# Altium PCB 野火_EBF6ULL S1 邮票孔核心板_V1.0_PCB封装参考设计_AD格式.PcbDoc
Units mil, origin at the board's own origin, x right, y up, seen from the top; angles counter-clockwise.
Board outline 50000 x 50000 mil, 2 copper layers (Signal, Signal #001), stack 10.4 mil thick; 1 components, 2 nets, 140 pads, 0 vias.
Unrouted connection lines stored in the file: 18.
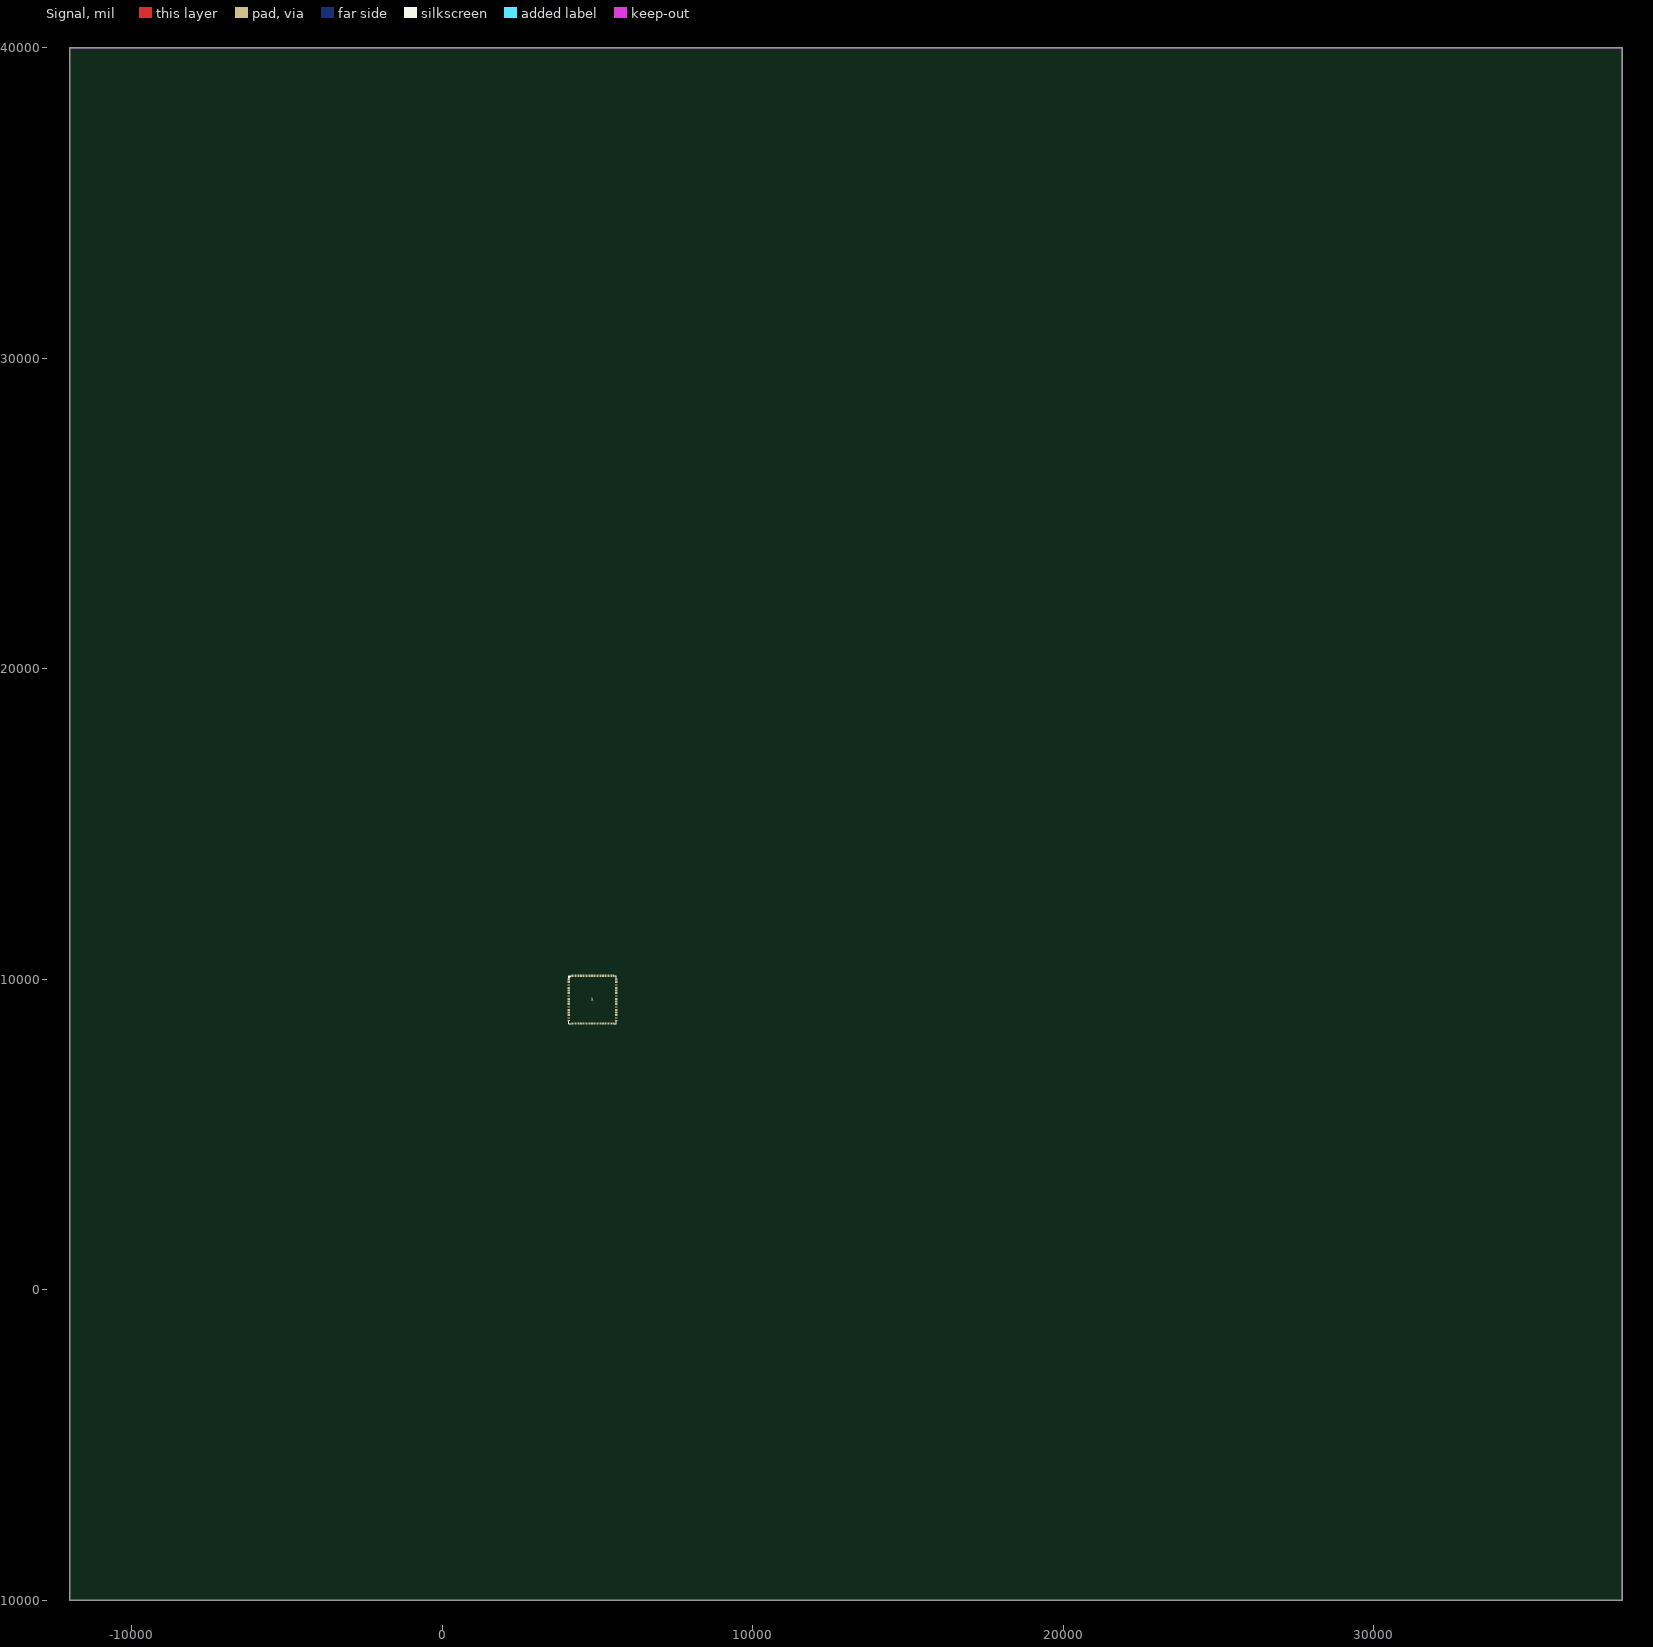
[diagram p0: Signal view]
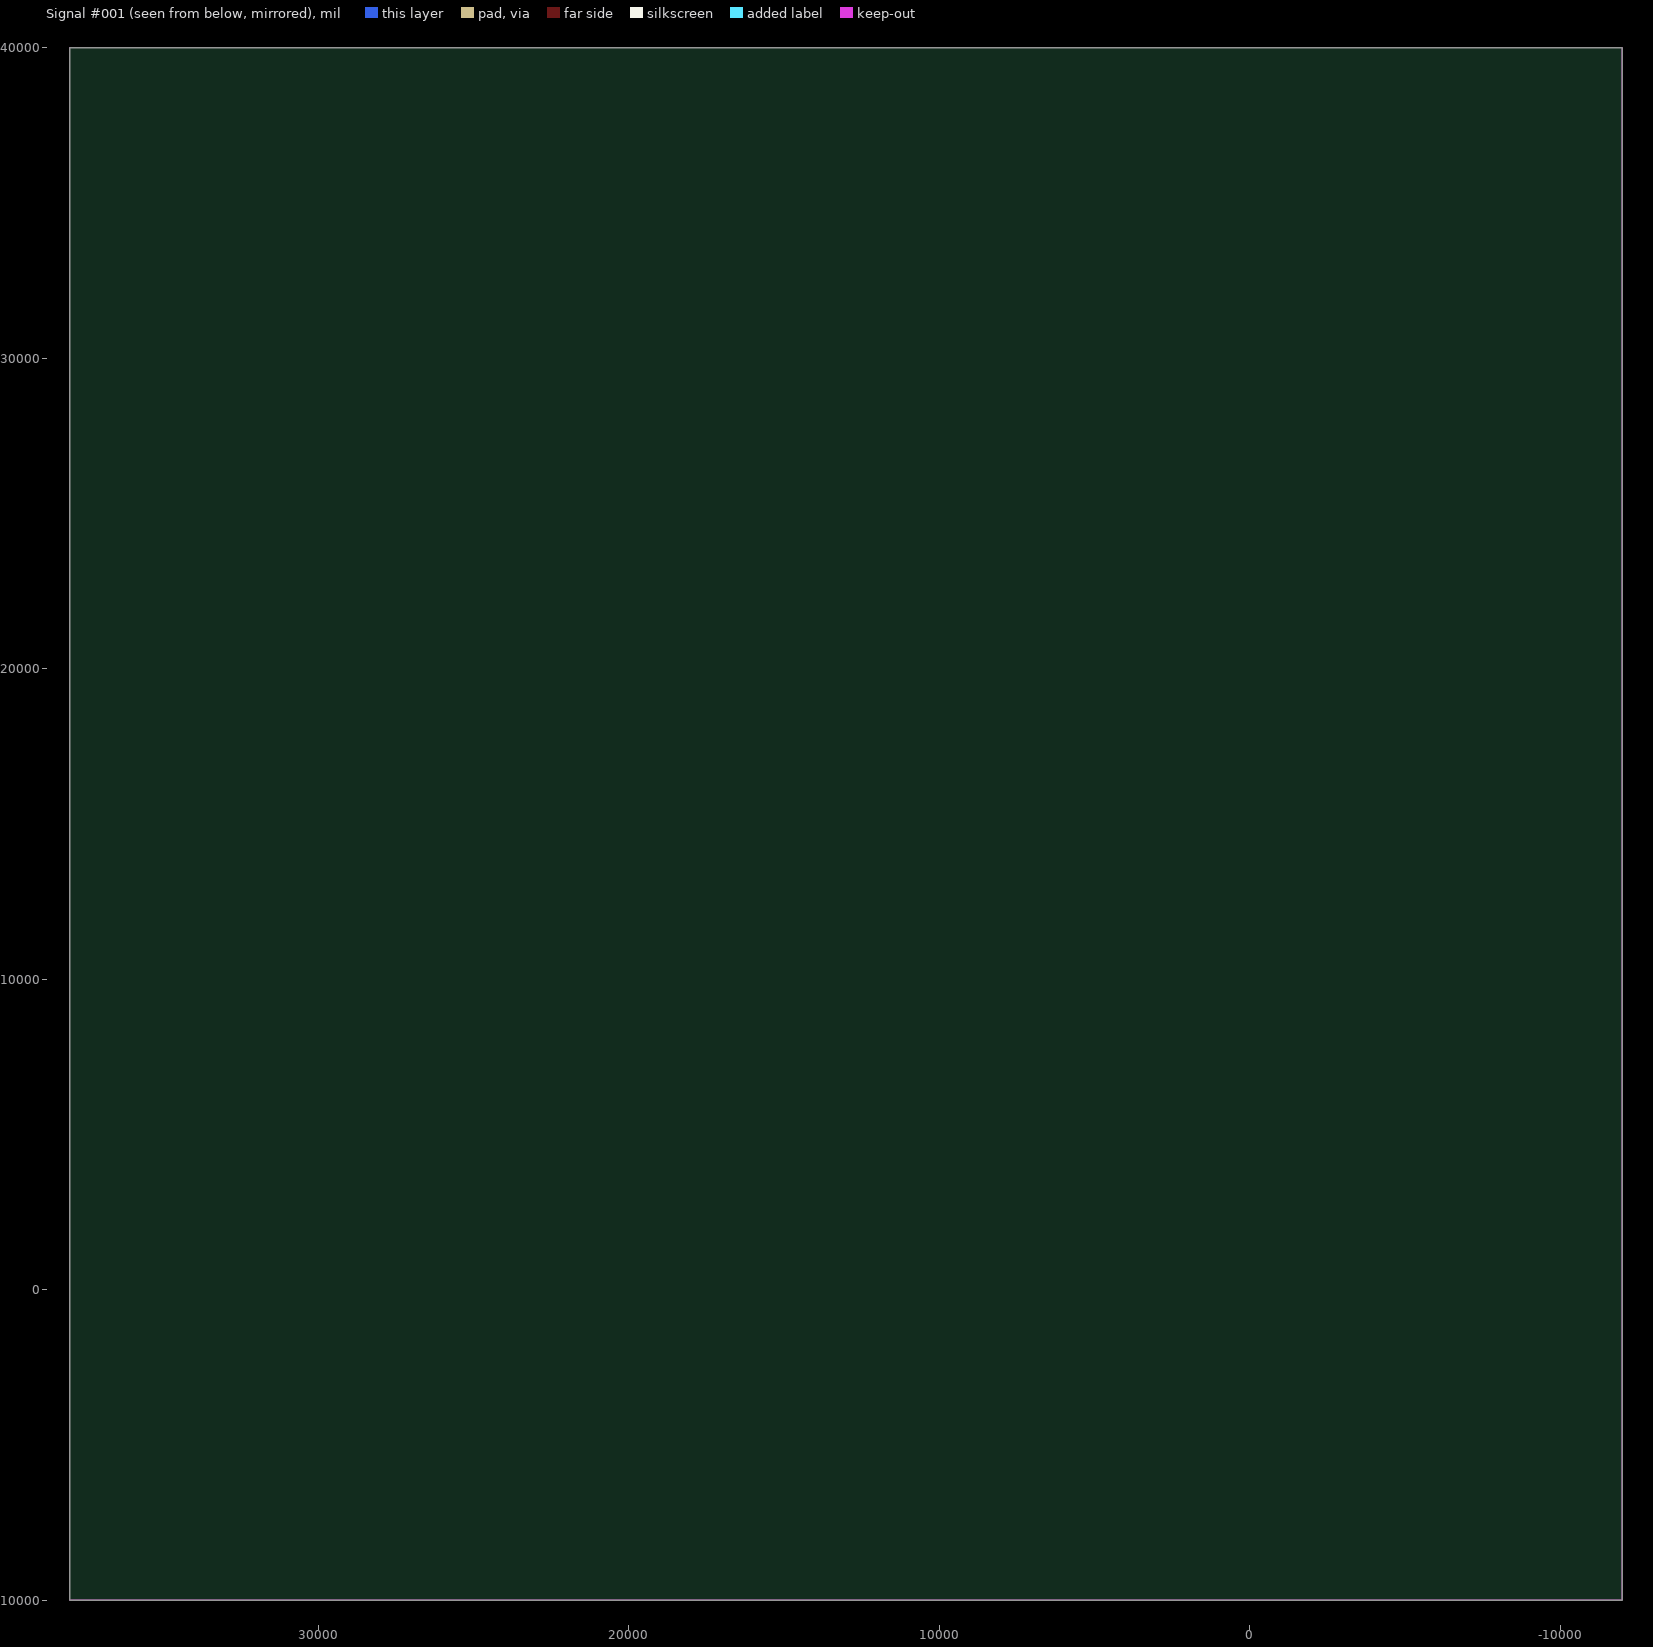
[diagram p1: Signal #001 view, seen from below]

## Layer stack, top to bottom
Solder Mask Top: solder mask 0.4, Solder Resist, Dk 3.5
Signal: signal copper 1.2
Dielectric 1: dielectric 8, FR-4, Dk 4.5
Signal #001: signal copper 1.2
Solder Mask Bottom: solder mask 0.4, Solder Resist, Dk 3.5

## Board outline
-12000,-10000 38000,-10000 38000,40000 -12000,40000

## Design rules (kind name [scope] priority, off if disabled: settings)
Clearance "Clearance - Net - GND- SMD" [InNet('GND') AND IsVia vs IsSMTPin] p1: gap=6 ignorepadtopadclearanceinfootprint=FALSE
Clearance "Clearance - Net - GND - Via" [InNet('GND') And IsVia vs IsVia] p2: gap=6 ignorepadtopadclearanceinfootprint=FALSE
Clearance "Clearance - Net - GND" [InNet('GND')] p3: gap=6 ignorepadtopadclearanceinfootprint=FALSE except(0: Arc-Hole Track-Hole SMDPad-Hole THPad-Hole Via-Hole Fill-Hole Poly-Hole Region-Hole Text-Hole; 8: Via-Fill Via-Poly Via-Region; 10: Fill-Fill Fill-Poly Fill-Region Poly-Poly Poly-Region Region-Region Text-Text; 15: Arc-Fill Arc-Poly Arc-Region Track-Fill Track-Poly Track-Region SMDPad-Fill SMDPad-Poly SMDPad-Region THPad-Fill THPad-Poly THPad-Region)
Clearance "Clearance - Default - DEFAULT- SMD" [IsVia vs IsSMTPin] p4: gap=5 ignorepadtopadclearanceinfootprint=FALSE
Clearance "Clearance - Default - DEFAULT - Via" [IsVia vs IsVia] p5: gap=5 ignorepadtopadclearanceinfootprint=FALSE
Clearance "Clearance - Default - DEFAULT - Net" [All] p6: gap=6 ignorepadtopadclearanceinfootprint=FALSE except(0: Arc-Hole Track-Hole SMDPad-Hole THPad-Hole Via-Hole Fill-Hole Poly-Hole Region-Hole Text-Hole; 5: Via-Via; 8: Via-Fill Via-Poly Via-Region; 10: SMDPad-Fill SMDPad-Poly SMDPad-Region THPad-Fill THPad-Poly THPad-Region Fill-Fill Fill-Poly Fill-Region Poly-Poly Poly-Region Region-Region Text-Text; 15: Arc-Fill Arc-Poly Arc-Region Track-Fill Track-Poly Track-Region)
ComponentClearance "ComponentClearance - Default - " [All] p1: gap=0 collisioncheckmode=3 verticalgap=10 showdistances=FALSE
ComponentClearance "ComponentClearance - Default - DEFAULT" [All] p2: gap=0 collisioncheckmode=3 verticalgap=10 showdistances=FALSE
FanoutControl Fanout_Small [(CompPinCount < 5)] p1: bgadir=Out bgaviamode=Centered fanoutstyle=Auto fanoutdirection=OutThenIn viagrid=1 // Fanout_Small (Default Rule)
FanoutControl Fanout_BGA [IsBGA] p4: bgadir=Out bgaviamode=Centered fanoutstyle=Auto fanoutdirection=Alternating viagrid=1 // Fanout_BGA (Default Rule)
HoleToHoleClearance "HoleToHoleClearance - Default - DEFAULT" [All] p1: gap=12 allowstackedmicrovias=TRUE
Length "Default Length" [All] p1: maxlimit=50000 minlimit=0
MaxMinImpedance "Default Impedance" [All] p1: minimum=50.00 maximum=150.0
ParallelSegment "Default Parallel Segment Adjasent" [All] p1: limit=1000 gap=200
ParallelSegment "Default Parallel Segment Same Layer" [All] p2: limit=1000 gap=200
RoutingLayers "RoutingLayers - Default - DEFAULT" [All] p1: top layer_v5=TRUE bottom layer_v5=TRUE
RoutingPriority "RoutingPriority - Default - DEFAULT" [All] p1: routingpriority=3
RoutingTopology "Default Routing Topology" [All] p1: topology=Shortest
RoutingVias "RoutingVias - Default - DEFAULT" [All] p1: holewidth=37 width=55 viastyle="Through Hole" minholewidth=37 minwidth=55 maxholewidth=37 maxwidth=55
SMDToCorner "SMDToCorner - Net - GND" [InNet('GND')] p1: distance=60000
SMDToCorner "SMDToCorner - Default - DEFAULT" [All] p2: distance=50000
SolderMaskExpansion [All] p1: expansion=4
Width "Width - Net - GND" [InNet('GND')] p1: maxlimit=7 minlimit=7 preferedwidth=7
Width "Width - NetClass - PWR" [InNetClass('PWR')] p2: maxlimit=7 minlimit=7 preferedwidth=7
Width "Default Width" [All] p3: maxlimit=6 minlimit=6 preferedwidth=6
Width "Default Width_1" [All] p4: maxlimit=6 minlimit=6 preferedwidth=6
20 further rules are at their usual default settings.

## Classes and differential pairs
net class PWR: 3V3_IN

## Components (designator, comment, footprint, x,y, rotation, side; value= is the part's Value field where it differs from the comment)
J12 "IMX6ULL_SOM_S1_140P_39X39" IMX6ULL_SOM_S1_140P_39X39 4838,9341 r90 top

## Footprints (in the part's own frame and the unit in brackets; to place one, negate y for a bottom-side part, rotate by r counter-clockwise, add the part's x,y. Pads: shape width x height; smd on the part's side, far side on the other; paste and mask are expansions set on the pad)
IMX6ULL_SOM_S1_140P_39X39 [mm]
  rect 0.6x2 smd mask+0.05: 1(17,19.5) 2(16,19.5) 3(15,19.5) 4(14,19.5) 5(13,19.5) 6(12,19.5) 7(11,19.5) 8(10,19.5) 9(9,19.5) 10(8,19.5) 11(7,19.5) 12(6,19.5) 13(5,19.5) 14(4,19.5) 15(3,19.5) 16(2,19.5) 17(1,19.5) 18(0,19.5) 19(-1,19.5) 20(-2,19.5) 21(-3,19.5) 22(-4,19.5) 23(-5,19.5) 24(-6,19.5) 25(-7,19.5) 26(-8,19.5) 27(-9,19.5) 28(-10,19.5) 29(-11,19.5) 30(-12,19.5) 31(-13,19.5) 32(-14,19.5) 33(-15,19.5) 34(-16,19.5) 35(-17,19.5) 71(-17,-19.5) 72(-16,-19.5) 73(-15,-19.5) 74(-14,-19.5) 75(-13,-19.5) 76(-12,-19.5) 77(-11,-19.5) 78(-10,-19.5) 79(-9,-19.5) 80(-8,-19.5) 81(-7,-19.5) 82(-6,-19.5) 83(-5,-19.5) 84(-4,-19.5) 85(-3,-19.5) 86(-2,-19.5) 87(-1,-19.5) 88(0,-19.5) 89(1,-19.5) 90(2,-19.5) 91(3,-19.5) 92(4,-19.5) 93(5,-19.5) 94(6,-19.5) 95(7,-19.5) 96(8,-19.5) 97(9,-19.5) 98(10,-19.5) 99(11,-19.5) 100(12,-19.5) 101(13,-19.5) 102(14,-19.5) 103(15,-19.5) 104(16,-19.5) 105(17,-19.5)
  rect 2x0.6 smd mask+0.05: 36(-19.5,17) 37(-19.5,16) 38(-19.5,15) 39(-19.5,14) 40(-19.5,13) 41(-19.5,12) 42(-19.5,11) 43(-19.5,10) 44(-19.5,9) 45(-19.5,8) 46(-19.5,7) 47(-19.5,6) 48(-19.5,5) 49(-19.5,4) 50(-19.5,3) 51(-19.5,2) 52(-19.5,1) 53(-19.5,0) 54(-19.5,-1) 55(-19.5,-2) 56(-19.5,-3) 57(-19.5,-4) 58(-19.5,-5) 59(-19.5,-6) 60(-19.5,-7) 61(-19.5,-8) 62(-19.5,-9) 63(-19.5,-10) 64(-19.5,-11) 65(-19.5,-12) 66(-19.5,-13) 67(-19.5,-14) 68(-19.5,-15) 69(-19.5,-16) 70(-19.5,-17) 106(19.5,-17) 107(19.5,-16) 108(19.5,-15) 109(19.5,-14) 110(19.5,-13) 111(19.5,-12) 112(19.5,-11) 113(19.5,-10) 114(19.5,-9) 115(19.5,-8) 116(19.5,-7) 117(19.5,-6) 118(19.5,-5) 119(19.5,-4) 120(19.5,-3) 121(19.5,-2) 122(19.5,-1) 123(19.5,0) 124(19.5,1) 125(19.5,2) 126(19.5,3) 127(19.5,4) 128(19.5,5) 129(19.5,6) 130(19.5,7) 131(19.5,8) 132(19.5,9) 133(19.5,10) 134(19.5,11) 135(19.5,12) 136(19.5,13) 137(19.5,14) 138(19.5,15) 139(19.5,16) 140(19.5,17)
  silkscreen extent -19.5,-19.5 19.5,19.5

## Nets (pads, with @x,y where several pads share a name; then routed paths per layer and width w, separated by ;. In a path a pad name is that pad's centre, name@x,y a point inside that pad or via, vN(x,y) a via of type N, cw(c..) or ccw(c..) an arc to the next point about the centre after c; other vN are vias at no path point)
3V3_IN: J12.138 J12.139 J12.140
GND: J12.9 J12.18 J12.27 J12.33 J12.40 J12.53 J12.64 J12.70 J12.77 J12.88 J12.92 J12.96 J12.115 J12.124 J12.133 J12.134 J12.135
pads on no net: J12.1 J12.2 J12.3 J12.4 J12.5 J12.6 J12.7 J12.8 J12.10 J12.11 J12.12 J12.13 J12.14 J12.15 J12.16 J12.17 J12.19 J12.20 J12.21 J12.22 J12.23 J12.24 J12.25 J12.26 J12.28 J12.29 J12.30 J12.31 J12.32 J12.34 J12.35 J12.36 J12.37 J12.38 J12.39 J12.41 J12.42 J12.43 J12.44 J12.45 J12.46 J12.47 J12.48 J12.49 J12.50 J12.51 J12.52 J12.54 J12.55 J12.56 J12.57 J12.58 J12.59 J12.60 J12.61 J12.62 J12.63 J12.65 J12.66 J12.67 J12.68 J12.69 J12.71 J12.72 J12.73 J12.74 J12.75 J12.76 J12.78 J12.79 J12.80 J12.81 J12.82 J12.83 J12.84 J12.85 J12.86 J12.87 J12.89 J12.90 J12.91 J12.93 J12.94 J12.95 J12.97 J12.98 J12.99 J12.100 J12.101 J12.102 J12.103 J12.104 J12.105 J12.106 J12.107 J12.108 J12.109 J12.110 J12.111 J12.112 J12.113 J12.114 J12.116 J12.117 J12.118 J12.119 J12.120 J12.121 J12.122 J12.123 J12.125 J12.126 J12.127 J12.128 J12.129 J12.130 J12.131 J12.132 J12.136 J12.137

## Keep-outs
Keep-Out Layer:
  the board outline again, w10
